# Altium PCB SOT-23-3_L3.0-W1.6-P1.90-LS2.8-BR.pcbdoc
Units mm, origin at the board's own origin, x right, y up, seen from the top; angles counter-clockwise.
Board outline 16.12 x 15.77 mm, 2 copper layers (Top Layer, Bottom Layer), stack 0 mm thick; 1 components, 0 nets, 3 pads, 0 vias.
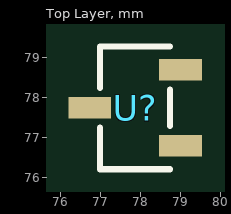
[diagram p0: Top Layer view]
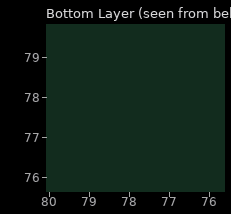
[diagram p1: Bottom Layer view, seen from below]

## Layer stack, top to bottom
Top Layer: signal copper (thickness not stored)
Bottom Layer: signal copper (thickness not stored)

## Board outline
85.971,69.85 69.85,69.85 69.85,85.622 85.971,85.622

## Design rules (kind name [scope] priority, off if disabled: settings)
PasteMaskExpansion "Paste Mask Expansion" [All] p1: expansion=0
SolderMaskExpansion "Solder Mask Expansion" [IsVia] p1: expansion=-25.4 istentingtop=TRUE
SolderMaskExpansion "Solder Mask Expansion" [All] p2: expansion=0.051 istentingtop=FALSE

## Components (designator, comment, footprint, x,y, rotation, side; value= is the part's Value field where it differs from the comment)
U? "" SOT-23-3_L3.0-W1.6-P1.90-LS2.8-BR 77.87,77.736 r0 top

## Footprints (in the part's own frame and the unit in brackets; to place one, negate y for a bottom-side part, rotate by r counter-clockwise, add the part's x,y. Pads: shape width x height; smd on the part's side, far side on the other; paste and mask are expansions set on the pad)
SOT-23-3_L3.0-W1.6-P1.90-LS2.8-BR [mm]
  rect 1.07x0.532 smd: 1(1.135,-0.95) 2(1.135,0.95) 3(-1.135,0)
  silkscreen extent -0.88,-1.54 0.88,1.54

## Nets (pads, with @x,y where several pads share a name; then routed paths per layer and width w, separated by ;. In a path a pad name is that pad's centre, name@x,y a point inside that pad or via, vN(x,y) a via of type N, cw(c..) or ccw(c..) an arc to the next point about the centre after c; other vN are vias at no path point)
pads on no net: U?.1 U?.2 U?.3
